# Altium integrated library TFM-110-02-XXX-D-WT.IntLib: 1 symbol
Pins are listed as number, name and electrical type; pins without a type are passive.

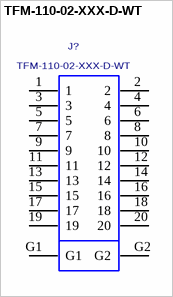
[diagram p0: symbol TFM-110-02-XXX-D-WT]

## TFM-110-02-XXX-D-WT
designator J?
0.050" TERMINAL STRIP, SURFACE MOUNT ASSEMBLY.; MANUFACTURER: SAMTEC
footprint TFM-110-02-XXX-D-WT
pins: 1, 2, 3, 4, 5, 6, 7, 8, 9, 10, 11, 12, 13, 14, 15, 16, 17, 18, 19, 20, G1, G2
